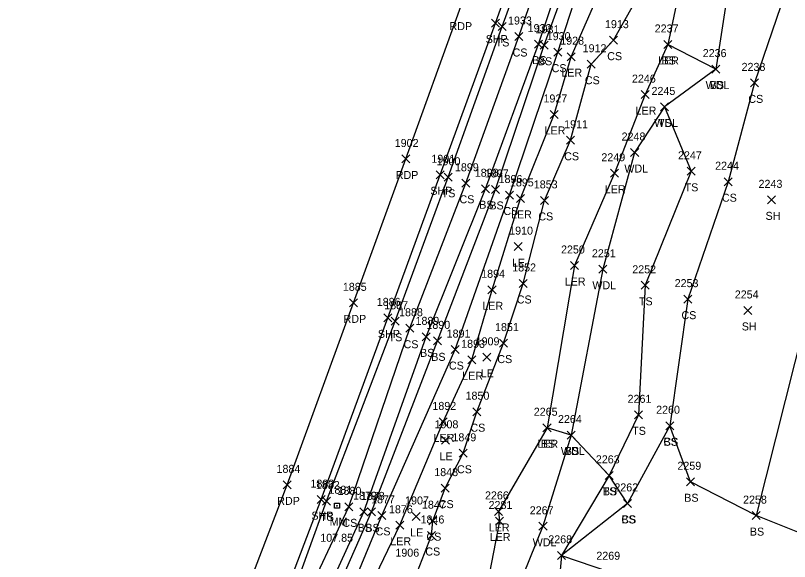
# Model space of a CAD drawing. Extents: x 1483143 to 1488182, y 802902 to 807581.
# Drawn here: x 1487817 to 1488010.4, y 806539 to 806675.5 of the extents above; entities that cross this region are included whole.
import ezdxf

# ---------------------------------------------------------------- set-up
doc = ezdxf.new("R2010")
doc.units = 0
for name, color, linetype in [('L_A', 7, 'Continuous'), ('L_I', 7, 'Continuous'), ('L_TIC', 7, 'Continuous'), ('LARO', 7, 'Continuous'), ('LAWA', 7, 'Continuous'), ('LELB', 7, 'Continuous'), ('P_A', 7, 'Continuous'), ('P_I', 7, 'Continuous'), ('P_TIC', 7, 'Continuous'), ('PET', 7, 'Continuous'), ('PSP', 7, 'Continuous'), ('S_A', 7, 'Continuous'), ('S_C', 7, 'Continuous'), ('S_I', 7, 'Continuous'), ('SRM', 7, 'Continuous')]:
    doc.layers.add(name, color=color, linetype=linetype)

msp = doc.modelspace()

# ---------------------------------------------------------------- linework, layer by layer
at = {"layer": 'L_TIC'}
for points in [[(1487937.6, 806671.73), (1487939.6, 806673.73)], [(1487939.6, 806671.73), (1487937.6, 806673.73)], [(1487941.79, 806669.21), (1487943.79, 806671.21)], [(1487943.79, 806669.21), (1487941.79, 806671.21)], [(1487965.43, 806668.3), (1487967.43, 806670.3)], [(1487967.43, 806668.3), (1487965.43, 806670.3)], [(1487946.69, 806667.31), (1487948.69, 806669.31)], [(1487948.69, 806667.31), (1487946.69, 806669.31)], [(1487948.11, 806667.02), (1487950.11, 806669.02)], [(1487950.11, 806667.02), (1487948.11, 806669.02)], [(1487978.99, 806667.22), (1487980.99, 806669.22)], [(1487980.99, 806667.22), (1487978.99, 806669.22)], [(1487978.99, 806667.22), (1487980.99, 806669.22)], [(1487980.99, 806667.22), (1487978.99, 806669.22)], [(1487951.54, 806665.3), (1487953.54, 806667.3)], [(1487953.54, 806665.3), (1487951.54, 806667.3)], [(1487954.83, 806664.17), (1487956.83, 806666.17)], [(1487956.83, 806664.17), (1487954.83, 806666.17)], [(1487959.85, 806662.28), (1487961.85, 806664.28)], [(1487961.85, 806662.28), (1487959.85, 806664.28)], [(1487991.04, 806661.06), (1487993.04, 806663.06)], [(1487993.04, 806661.06), (1487991.04, 806663.06)], [(1487991.04, 806661.06), (1487993.04, 806663.06)], [(1487993.04, 806661.06), (1487991.04, 806663.06)], [(1488000.7, 806657.62), (1488002.7, 806659.62)], [(1488002.7, 806657.62), (1488000.7, 806659.62)], [(1487973.36, 806654.69), (1487975.36, 806656.69)], [(1487975.36, 806654.69), (1487973.36, 806656.69)], [(1487978.2, 806651.61), (1487980.2, 806653.61)], [(1487980.2, 806651.61), (1487978.2, 806653.61)], [(1487978.2, 806651.61), (1487980.2, 806653.61)], [(1487980.2, 806651.61), (1487978.2, 806653.61)], [(1487950.65, 806649.73), (1487952.65, 806651.73)], [(1487952.65, 806649.73), (1487950.65, 806651.73)], [(1487954.68, 806643.28), (1487956.68, 806645.28)], [(1487956.68, 806643.28), (1487954.68, 806645.28)], [(1487970.73, 806640.22), (1487972.73, 806642.22)], [(1487972.73, 806640.22), (1487970.73, 806642.22)], [(1487984.81, 806635.52), (1487986.81, 806637.52)], [(1487986.81, 806635.52), (1487984.81, 806637.52)], [(1487924.11, 806634.03), (1487926.11, 806636.03)], [(1487926.11, 806634.03), (1487924.11, 806636.03)], [(1487965.68, 806635.04), (1487967.68, 806637.04)], [(1487967.68, 806635.04), (1487965.68, 806637.04)], [(1487928.53, 806632.53), (1487930.53, 806634.53)], [(1487930.53, 806632.53), (1487928.53, 806634.53)], [(1487994.09, 806632.92), (1487996.09, 806634.92)], [(1487996.09, 806632.92), (1487994.09, 806634.92)], [(1487933.47, 806631.17), (1487935.47, 806633.17)], [(1487935.47, 806631.17), (1487933.47, 806633.17)], [(1487936, 806630.99), (1487938, 806632.99)], [(1487938, 806630.99), (1487936, 806632.99)], [(1487939.49, 806629.59), (1487941.49, 806631.59)], [(1487941.49, 806629.59), (1487939.49, 806631.59)], [(1487942.25, 806628.75), (1487944.25, 806630.75)], [(1487944.25, 806628.75), (1487942.25, 806630.75)], [(1487948.22, 806628.25), (1487950.22, 806630.25)], [(1487950.22, 806628.25), (1487948.22, 806630.25)], [(1488004.94, 806628.39), (1488006.94, 806630.39)], [(1488006.94, 806628.39), (1488004.94, 806630.39)], [(1487941.59, 806616.7), (1487943.59, 806618.7)], [(1487943.59, 806616.7), (1487941.59, 806618.7)], [(1487955.68, 806611.98), (1487957.68, 806613.98)], [(1487957.68, 806611.98), (1487955.68, 806613.98)], [(1487962.74, 806611.04), (1487964.74, 806613.04)], [(1487964.74, 806611.04), (1487962.74, 806613.04)], [(1487942.84, 806607.49), (1487944.84, 806609.49)], [(1487944.84, 806607.49), (1487942.84, 806609.49)], [(1487973.39, 806607.03), (1487975.39, 806609.03)], [(1487975.39, 806607.03), (1487973.39, 806609.03)], [(1487935.09, 806605.91), (1487937.09, 806607.91)], [(1487937.09, 806605.91), (1487935.09, 806607.91)], [(1487983.98, 806603.57), (1487985.98, 806605.57)], [(1487985.98, 806603.57), (1487983.98, 806605.57)], [(1487999, 806600.75), (1488001, 806602.75)], [(1488001, 806600.75), (1487999, 806602.75)], [(1487910.86, 806598.05), (1487912.86, 806600.05)], [(1487912.86, 806598.05), (1487910.86, 806600.05)], [(1487914.56, 806596.3), (1487916.56, 806598.3)], [(1487916.56, 806596.3), (1487914.56, 806598.3)], [(1487918.68, 806594.15), (1487920.68, 806596.15)], [(1487920.68, 806594.15), (1487918.68, 806596.15)], [(1487921.48, 806593.15), (1487923.48, 806595.15)], [(1487923.48, 806593.15), (1487921.48, 806595.15)], [(1487925.89, 806590.97), (1487927.89, 806592.97)], [(1487927.89, 806590.97), (1487925.89, 806592.97)], [(1487937.98, 806592.59), (1487939.98, 806594.59)], [(1487939.98, 806592.59), (1487937.98, 806594.59)], [(1487933.78, 806589.03), (1487935.78, 806591.03)], [(1487935.78, 806589.03), (1487933.78, 806591.03)], [(1487930.07, 806588.41), (1487932.07, 806590.41)], [(1487932.07, 806588.41), (1487930.07, 806590.41)], [(1487931.26, 806575.44), (1487933.26, 806577.44)], [(1487933.26, 806575.44), (1487931.26, 806577.44)], [(1487971.7, 806574.66), (1487973.7, 806576.66)], [(1487973.7, 806574.66), (1487971.7, 806576.66)], [(1487922.9, 806572.89), (1487924.9, 806574.89)], [(1487924.9, 806572.89), (1487922.9, 806574.89)], [(1487979.48, 806571.93), (1487981.48, 806573.93)], [(1487981.48, 806571.93), (1487979.48, 806573.93)], [(1487979.48, 806571.93), (1487981.48, 806573.93)], [(1487981.48, 806571.93), (1487979.48, 806573.93)], [(1487948.83, 806571.43), (1487950.83, 806573.43)], [(1487950.83, 806571.43), (1487948.83, 806573.43)], [(1487948.83, 806571.43), (1487950.83, 806573.43)], [(1487950.83, 806571.43), (1487948.83, 806573.43)], [(1487923.51, 806568.29), (1487925.51, 806570.29)], [(1487925.51, 806568.29), (1487923.51, 806570.29)], [(1487954.87, 806569.61), (1487956.87, 806571.61)], [(1487956.87, 806569.61), (1487954.87, 806571.61)], [(1487954.87, 806569.61), (1487956.87, 806571.61)], [(1487956.87, 806569.61), (1487954.87, 806571.61)], [(1487927.91, 806565.05), (1487929.91, 806567.05)], [(1487929.91, 806565.05), (1487927.91, 806567.05)], [(1487964.34, 806559.53), (1487966.34, 806561.53)], [(1487966.34, 806559.53), (1487964.34, 806561.53)], [(1487964.34, 806559.53), (1487966.34, 806561.53)], [(1487966.34, 806559.53), (1487964.34, 806561.53)], [(1487923.36, 806556.34), (1487925.36, 806558.34)], [(1487925.36, 806556.34), (1487923.36, 806558.34)], [(1487984.68, 806557.93), (1487986.68, 806559.93)], [(1487986.68, 806557.93), (1487984.68, 806559.93)], [(1487893.77, 806553.11), (1487895.77, 806555.11)], [(1487895.77, 806553.11), (1487893.77, 806555.11)], [(1487968.96, 806552.52), (1487970.96, 806554.52)], [(1487970.96, 806552.52), (1487968.96, 806554.52)], [(1487968.96, 806552.52), (1487970.96, 806554.52)], [(1487970.96, 806552.52), (1487968.96, 806554.52)], [(1487899.29, 806551.66), (1487901.29, 806553.66)], [(1487901.29, 806551.66), (1487899.29, 806553.66)], [(1487903.08, 806550.45), (1487905.08, 806552.45)], [(1487905.08, 806550.45), (1487903.08, 806552.45)], [(1487905.02, 806550.4), (1487907.02, 806552.4)], [(1487907.02, 806550.4), (1487905.02, 806552.4)], [(1487936.7, 806550.52), (1487938.7, 806552.52)], [(1487938.7, 806550.52), (1487936.7, 806552.52)], [(1487907.57, 806549.53), (1487909.57, 806551.53)], [(1487909.57, 806549.53), (1487907.57, 806551.53)], [(1487916.15, 806549.26), (1487918.15, 806551.26)], [(1487918.15, 806549.26), (1487916.15, 806551.26)], [(1488001.07, 806549.47), (1488003.07, 806551.47)], [(1488003.07, 806549.47), (1488001.07, 806551.47)], [(1488001.07, 806549.47), (1488003.07, 806551.47)], [(1488003.07, 806549.47), (1488001.07, 806551.47)], [(1487912.1, 806547.05), (1487914.1, 806549.05)], [(1487914.1, 806547.05), (1487912.1, 806549.05)], [(1487920.28, 806548.2), (1487922.28, 806550.2)], [(1487922.28, 806548.2), (1487920.28, 806550.2)], [(1487936.93, 806548.12), (1487938.93, 806550.12)], [(1487938.93, 806548.12), (1487936.93, 806550.12)], [(1487947.83, 806546.8), (1487949.83, 806548.8)], [(1487949.83, 806546.8), (1487947.83, 806548.8)], [(1487919.99, 806544.5), (1487921.99, 806546.5)], [(1487921.99, 806544.5), (1487919.99, 806546.5)], [(1487952.46, 806539.54), (1487954.46, 806541.54)], [(1487954.46, 806539.54), (1487952.46, 806541.54)], [(1487952.46, 806539.54), (1487954.46, 806541.54)], [(1487954.46, 806539.54), (1487952.46, 806541.54)]]:
    msp.add_lwpolyline(points, dxfattribs=at)
at = {"layer": 'LARO'}
for points in [[(1488009.53, 806779.63), (1488008.11, 806762.07), (1487997.19, 806745.28), (1487993.76, 806718.32), (1487985.65, 806695.01), (1487979.99, 806668.22), (1487974.36, 806655.69), (1487966.68, 806636.04), (1487956.68, 806612.98), (1487949.83, 806572.43), (1487937.7, 806551.52), (1487937.93, 806549.12), (1487933.98, 806528.45), (1487931.33, 806504.22), (1487936.03, 806486.24), (1487936.87, 806458.71), (1487938.26, 806448.96), (1487936.18, 806429.85), (1487938.33, 806405.75), (1487927.08, 806402.62)], [(1487852.63, 806386.9), (1487863.18, 806416.3), (1487866.91, 806430.49), (1487877.32, 806448.58), (1487880.97, 806452.79), (1487881.3, 806467.05), (1487891.05, 806491.04), (1487900.99, 806522.93), (1487913.1, 806548.05), (1487923.9, 806573.89), (1487931.07, 806589.41), (1487936.09, 806606.91), (1487943.25, 806629.75), (1487951.65, 806650.73), (1487955.83, 806665.17), (1487963.5, 806682.75)]]:
    msp.add_lwpolyline(points, dxfattribs=at)
at = {"layer": 'LAWA'}
msp.add_lwpolyline([(1488013.56, 806779), (1488014.78, 806760.28), (1488003.55, 806746.14), (1488000.09, 806716.32), (1487996.76, 806693.07), (1487992.04, 806662.06), (1487979.2, 806652.61), (1487971.73, 806641.22), (1487963.74, 806612.04), (1487955.87, 806570.61), (1487948.83, 806547.8), (1487940.57, 806527.46), (1487937.43, 806503.41), (1487936.03, 806486.24), (1487944.09, 806456.8), (1487943.56, 806449.98), (1487942.37, 806424.18), (1487942.13, 806400.96)], dxfattribs=at)
at = {"layer": 'LELB'}
for points in [[(1487827.52, 806379.6), (1487850.09, 806437.73), (1487867.87, 806481.84), (1487885.56, 806528.78), (1487894.77, 806554.11), (1487911.86, 806599.05), (1487925.11, 806635.03), (1487938.6, 806672.73), (1487954.13, 806715.2), (1487966.77, 806750.86), (1487982.82, 806798.37), (1488000.33, 806849.53), (1488013.76, 806891.57), (1488028.96, 806936.12), (1488043.22, 806981), (1488053.37, 807013.21), (1488065.46, 807054.1), (1488079.1, 807097.32), (1488091.92, 807141.06), (1488105.94, 807188.64)], [(1487831.61, 806378.23), (1487855.61, 806436.65), (1487873.41, 806477.14), (1487888.61, 806527.7), (1487900.29, 806552.66), (1487915.56, 806597.3), (1487929.53, 806633.53), (1487942.79, 806670.21), (1487957.7, 806713.57), (1487969.99, 806749.64), (1487987.61, 806796.79), (1487994.35, 806813.4), (1488006.31, 806847.85), (1488017.75, 806890.1), (1488033.51, 806934.67), (1488047.05, 806979.87), (1488058.1, 807011.89), (1488070.58, 807052.35), (1488082.44, 807096.83), (1488095.42, 807139.95), (1488114.02, 807186.94)], [(1487835.19, 806376.59), (1487859.78, 806434.97), (1487877.62, 806477.28), (1487892.57, 806526.23), (1487904.08, 806551.45), (1487919.68, 806595.15), (1487934.47, 806632.17), (1487947.69, 806668.31), (1487962.32, 806711.59), (1487973.69, 806748.32), (1487991.68, 806795.65), (1487997.75, 806809.49), (1487999.54, 806813.18), (1488009.67, 806846.56), (1488021.34, 806888.06), (1488037.67, 806932.78), (1488051.91, 806977.51), (1488062.67, 807010.29), (1488074.95, 807051.31), (1488088, 807095.72), (1488100.03, 807138.12), (1488122.67, 807183.2)], [(1487837.5, 806376), (1487863.45, 806433.38), (1487880.32, 806475.86), (1487894.61, 806525.53), (1487906.02, 806551.4), (1487922.48, 806594.15), (1487937, 806631.99), (1487949.11, 806668.02), (1487964.79, 806711), (1487978.4, 806746.47), (1487994.99, 806794.38), (1488000.35, 806808.82), (1488001.34, 806812.09), (1488011.23, 806845.63), (1488024.65, 806886.78), (1488040.19, 806931.5), (1488054.27, 806976.88), (1488065.68, 807009.57), (1488076.91, 807050.77), (1488090.18, 807095.37), (1488103.15, 807137.16), (1488127.49, 807179.54)], [(1487839.66, 806374.66), (1487865.87, 806433.14), (1487881.15, 806476.22), (1487897.55, 806523.91), (1487908.57, 806550.53), (1487926.89, 806591.97), (1487940.49, 806630.59), (1487952.54, 806666.3), (1487966.7, 806710.04), (1487981.74, 806745.96), (1487997.33, 806793.52), (1488011.64, 806832), (1488027.95, 806886.11), (1488041.92, 806927.39), (1488045.38, 806935.91), (1488056.2, 806975.87), (1488068.38, 807008.79), (1488080.46, 807050.29), (1488092.26, 807094.39), (1488105.79, 807135.26), (1488129.48, 807176.06)], [(1488039.63, 806814.37), (1488031.14, 806790.78), (1488032.93, 806764.39), (1488017.53, 806734.89), (1488014.76, 806696.96), (1488001.7, 806658.62), (1487995.09, 806633.92), (1487984.98, 806604.57), (1487980.48, 806572.93), (1487969.96, 806553.52), (1487953.46, 806540.54), (1487965.47, 806536.44), (1487984.45, 806521.74), (1488004.88, 806498.25)], [(1488057.62, 806804.31), (1488053.28, 806778.75), (1488055.57, 806759.29), (1488045.22, 806727.88), (1488037.59, 806692.17), (1488022.17, 806654.43), (1488019.2, 806624.46), (1488014.13, 806598.44), (1488002.07, 806550.47)], [(1487915.7, 806531.99), (1487920.99, 806545.5), (1487921.28, 806549.2), (1487924.36, 806557.34), (1487928.91, 806566.05), (1487932.26, 806576.44), (1487938.98, 806593.59), (1487943.84, 806608.49), (1487949.22, 806629.25), (1487955.68, 806644.28), (1487960.85, 806663.28), (1487966.43, 806669.3), (1487974.79, 806684.14)], [(1487992.04, 806662.06), (1487979.99, 806668.22)], [(1487979.2, 806652.61), (1487985.81, 806636.52), (1487974.39, 806608.03), (1487972.7, 806575.66), (1487965.34, 806560.53), (1487953.46, 806540.54), (1487952.14, 806525.79), (1487961.18, 806514.49), (1487969.24, 806499.88), (1487972.36, 806481.07), (1487971.79, 806474.55), (1487983.36, 806461.18)], [(1487969.96, 806553.52), (1487965.34, 806560.53), (1487955.87, 806570.61), (1487949.83, 806572.43)], [(1488015.01, 806545.3), (1488002.07, 806550.47), (1487985.68, 806558.93), (1487980.48, 806572.93)]]:
    msp.add_lwpolyline(points, dxfattribs=at)
at = {"layer": 'P_TIC'}
for points in [[(1487935.98, 806672.57), (1487937.98, 806674.57)], [(1487937.98, 806672.57), (1487935.98, 806674.57)], [(1487913.56, 806638.6), (1487915.56, 806640.6)], [(1487915.56, 806638.6), (1487913.56, 806640.6)], [(1487922.16, 806634.65), (1487924.16, 806636.65)], [(1487924.16, 806634.65), (1487922.16, 806636.65)], [(1487900.52, 806602.65), (1487902.52, 806604.65)], [(1487902.52, 806602.65), (1487900.52, 806604.65)], [(1487909.05, 806598.89), (1487911.05, 806600.89)], [(1487911.05, 806598.89), (1487909.05, 806600.89)], [(1487883.95, 806557.16), (1487885.95, 806559.16)], [(1487885.95, 806557.16), (1487883.95, 806559.16)], [(1487892.44, 806553.46), (1487894.44, 806555.46)], [(1487894.44, 806553.46), (1487892.44, 806555.46)]]:
    msp.add_lwpolyline(points, dxfattribs=at)
at = {"layer": 'PET'}
msp.add_lwpolyline([(1487817.05, 806384.04), (1487839.67, 806441.4), (1487857.48, 806486.15), (1487875.5, 806533.55), (1487884.95, 806558.16), (1487901.52, 806603.65), (1487914.56, 806639.6), (1487927.99, 806676.8), (1487943.06, 806720.01), (1487955.19, 806754.64), (1487971.37, 806801.63), (1487988.85, 806854.11), (1488002.85, 806896.07), (1488017.7, 806940.87), (1488031.56, 806984.9), (1488041.8, 807017.08), (1488054.37, 807058.25), (1488067.6, 807101.48), (1488080.81, 807144.82), (1488095.07, 807192.49)], dxfattribs=at)
at = {"layer": 'PSP'}
msp.add_lwpolyline([(1487825.55, 806380.21), (1487847.81, 806437.56), (1487866.19, 806483.39), (1487884.04, 806529.78), (1487893.44, 806554.46), (1487910.05, 806599.89), (1487923.16, 806635.65), (1487936.98, 806673.57), (1487951.99, 806715.79), (1487964.7, 806751.7), (1487980.81, 806798.97), (1487998.23, 806850.18), (1488012.19, 806892.24), (1488027.11, 806936.91), (1488041.21, 806981.53), (1488051.31, 807013.35), (1488064.14, 807054.93), (1488077.14, 807097.61), (1488090.36, 807141.77), (1488104.31, 807189.57)], dxfattribs=at)
at = {"layer": 'SRM'}
msp.add_lwpolyline([(1487896.73, 806553.55), (1487897.98, 806553.55), (1487897.98, 806552.3), (1487896.73, 806552.3)], close=True, dxfattribs=at)
msp.add_circle((1487897.35, 806552.93), 0.0833, dxfattribs=at)

# ---------------------------------------------------------------- texts
at = {"layer": 'L_A'}
for s, p in [('TS', (1487937.01, 806667.73)), ('CS', (1487941.23, 806665.21)), ('BS', (1487946.13, 806663.31)), ('BS', (1487947.56, 806663.02)), ('CS', (1487964.87, 806664.3)), ('LER', (1487977.58, 806663.22)), ('BS', (1487978.43, 806663.22)), ('CS', (1487950.98, 806661.3)), ('LER', (1487953.41, 806660.17)), ('CS', (1487959.29, 806658.28)), ('WDL', (1487989.46, 806657.06)), ('BS', (1487990.48, 806657.06)), ('CS', (1488000.14, 806653.62)), ('LER', (1487971.95, 806650.69)), ('WDL', (1487976.62, 806647.61)), ('TS', (1487977.61, 806647.61)), ('LER', (1487949.23, 806645.73)), ('CS', (1487954.12, 806639.28)), ('WDL', (1487969.15, 806636.22)), ('TS', (1487984.22, 806631.52)), ('TS', (1487923.52, 806630.03)), ('LER', (1487964.26, 806631.04)), ('CS', (1487927.97, 806628.53)), ('CS', (1487993.53, 806628.92)), ('BS', (1487932.91, 806627.17)), ('BS', (1487935.44, 806626.99)), ('CS', (1487938.93, 806625.59)), ('LER', (1487940.84, 806624.75)), ('CS', (1487947.66, 806624.25)), ('SH', (1488004.43, 806624.39)), ('LE', (1487941.08, 806612.7)), ('LER', (1487954.26, 806607.98)), ('WDL', (1487961.16, 806607.04)), ('CS', (1487942.28, 806603.49)), ('TS', (1487972.8, 806603.03)), ('LER', (1487933.67, 806601.91)), ('CS', (1487983.42, 806599.57)), ('SH', (1487998.49, 806596.75)), ('TS', (1487910.27, 806594.05)), ('CS', (1487914, 806592.3)), ('BS', (1487918.12, 806590.15)), ('BS', (1487920.92, 806589.15)), ('CS', (1487937.42, 806588.59)), ('CS', (1487925.33, 806586.97)), ('LER', (1487928.65, 806584.41)), ('LE', (1487933.27, 806585.03)), ('CS', (1487930.7, 806571.44)), ('TS', (1487971.11, 806570.66)), ('LER', (1487921.48, 806568.89)), ('CS', (1487978.92, 806567.93)), ('BS', (1487978.92, 806567.93)), ('LER', (1487947.41, 806567.43)), ('BS', (1487948.27, 806567.43)), ('LE', (1487923, 806564.29)), ('WDL', (1487953.29, 806565.61)), ('BS', (1487954.31, 806565.61)), ('CS', (1487927.35, 806561.05)), ('TS', (1487963.75, 806555.53)), ('BS', (1487963.78, 806555.53)), ('CS', (1487922.8, 806552.34)), ('BS', (1487984.12, 806553.93)), ('TS', (1487893.18, 806549.11)), ('CS', (1487968.4, 806548.52)), ('BS', (1487968.4, 806548.52)), ('CS', (1487898.73, 806547.66)), ('BS', (1487902.52, 806546.45)), ('BS', (1487904.46, 806546.4)), ('LER', (1487935.28, 806546.52)), ('CS', (1487907.01, 806545.53)), ('LE', (1487915.64, 806545.26)), ('BS', (1488000.51, 806545.47)), ('BS', (1488000.51, 806545.47)), ('LER', (1487910.68, 806543.05)), ('CS', (1487919.72, 806544.2)), ('LER', (1487935.51, 806544.12)), ('WDL', (1487946.25, 806542.8)), ('CS', (1487919.43, 806540.5))]:
    msp.add_text(s, height=2, dxfattribs=at).set_placement(p)
at = {"layer": 'L_I'}
for s, p in [('1933', (1487940.09, 806673.21)), ('1913', (1487964.31, 806672.3)), ('1932', (1487944.99, 806671.31)), ('1931', (1487946.99, 806671.02)), ('2237', (1487976.73, 806671.22)), ('2237', (1487976.73, 806671.22)), ('1930', (1487949.76, 806669.3)), ('1928', (1487953.13, 806668.17)), ('1912', (1487958.73, 806666.28)), ('2236', (1487988.73, 806665.06)), ('2236', (1487988.73, 806665.06)), ('2238', (1487998.44, 806661.62)), ('2246', (1487971.05, 806658.69)), ('2245', (1487975.94, 806655.61)), ('2245', (1487975.94, 806655.61)), ('1927', (1487948.95, 806653.73)), ('1911', (1487954.12, 806647.28)), ('2248', (1487968.47, 806644.22)), ('2247', (1487982.55, 806639.52)), ('1900', (1487922.26, 806638.03)), ('2249', (1487963.41, 806639.04)), ('1899', (1487926.83, 806636.53)), ('2244', (1487991.83, 806636.92)), ('1898', (1487931.78, 806635.17)), ('1897', (1487934.31, 806634.99)), ('1896', (1487937.74, 806633.59)), ('1895', (1487940.56, 806632.75)), ('1853', (1487946.53, 806632.25)), ('2243', (1488002.68, 806632.39)), ('1910', (1487940.38, 806620.7)), ('2250', (1487953.33, 806615.98)), ('2251', (1487961.05, 806615.04)), ('1852', (1487941.14, 806611.49)), ('2252', (1487971.13, 806611.03)), ('1894', (1487933.39, 806609.91)), ('2253', (1487981.72, 806607.57)), ('2254', (1487996.74, 806604.75)), ('1887', (1487909.17, 806602.05)), ('1888', (1487912.87, 806600.3)), ('1889', (1487916.98, 806598.15)), ('1890', (1487919.7, 806597.15)), ('1891', (1487924.76, 806594.97)), ('1851', (1487936.85, 806596.59)), ('1909', (1487932, 806593.03)), ('1893', (1487928.38, 806592.41)), ('1850', (1487929.48, 806579.44)), ('2261', (1487969.96, 806578.66)), ('1892', (1487921.2, 806576.89)), ('2265', (1487946.52, 806575.43)), ('2265', (1487946.52, 806575.43)), ('2260', (1487977.09, 806575.93)), ('2260', (1487977.09, 806575.93)), ('2264', (1487952.57, 806573.61)), ('2264', (1487952.57, 806573.61)), ('1908', (1487921.74, 806572.29)), ('1849', (1487926.21, 806569.05)), ('2263', (1487962.03, 806563.53)), ('2263', (1487962.03, 806563.53)), ('2259', (1487982.41, 806561.93)), ('1848', (1487921.67, 806560.34)), ('1882', (1487892.07, 806557.11)), ('2262', (1487966.65, 806556.52)), ('2262', (1487966.65, 806556.52)), ('1880', (1487897.51, 806555.66)), ('1879', (1487901.38, 806554.45)), ('1878', (1487903.33, 806554.4)), ('2266', (1487934.34, 806554.52)), ('1877', (1487905.88, 806553.53)), ('1907', (1487914.38, 806553.26)), ('1847', (1487918.59, 806552.2)), ('2258', (1487998.81, 806553.47)), ('2258', (1487998.81, 806553.47)), ('1876', (1487910.35, 806551.05)), ('2281', (1487935.23, 806552.12)), ('2267', (1487945.52, 806550.8)), ('1846', (1487918.24, 806548.5)), ('2268', (1487950.15, 806543.54)), ('2268', (1487950.15, 806543.54)), ('1906', (1487911.95, 806540.21)), ('2269', (1487962.15, 806539.44))]:
    msp.add_text(s, height=2, dxfattribs=at).set_placement(p)
at = {"layer": 'P_A'}
for s, p in [('RDP', (1487925.48, 806671.8)), ('SHP', (1487934.52, 806668.57)), ('RDP', (1487912.05, 806634.6)), ('SHP', (1487920.69, 806630.65)), ('RDP', (1487899.01, 806598.65)), ('SHP', (1487907.58, 806594.89)), ('RDP', (1487882.44, 806553.16)), ('SHP', (1487890.97, 806549.46))]:
    msp.add_text(s, height=2, dxfattribs=at).set_placement(p)
at = {"layer": 'P_I'}
for s, p in [('1902', (1487911.79, 806642.6)), ('1901', (1487920.95, 806638.65)), ('1885', (1487898.83, 806606.65)), ('1886', (1487907.3, 806602.89)), ('1884', (1487882.26, 806561.16)), ('1883', (1487890.74, 806557.46))]:
    msp.add_text(s, height=2, dxfattribs=at).set_placement(p)
at = {"layer": 'S_A'}
msp.add_text('MM', height=2, dxfattribs=at).set_placement((1487895.54, 806547.93))
at = {"layer": 'S_C'}
msp.add_text('107.85', height=2, dxfattribs=at).set_placement((1487893.19, 806543.93))
at = {"layer": 'S_I'}
msp.add_text('1881', height=2, dxfattribs=at).set_placement((1487895.23, 806555.93))

doc.saveas('drawing.dxf')
